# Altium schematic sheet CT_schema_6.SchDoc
size 255 x 245 mm
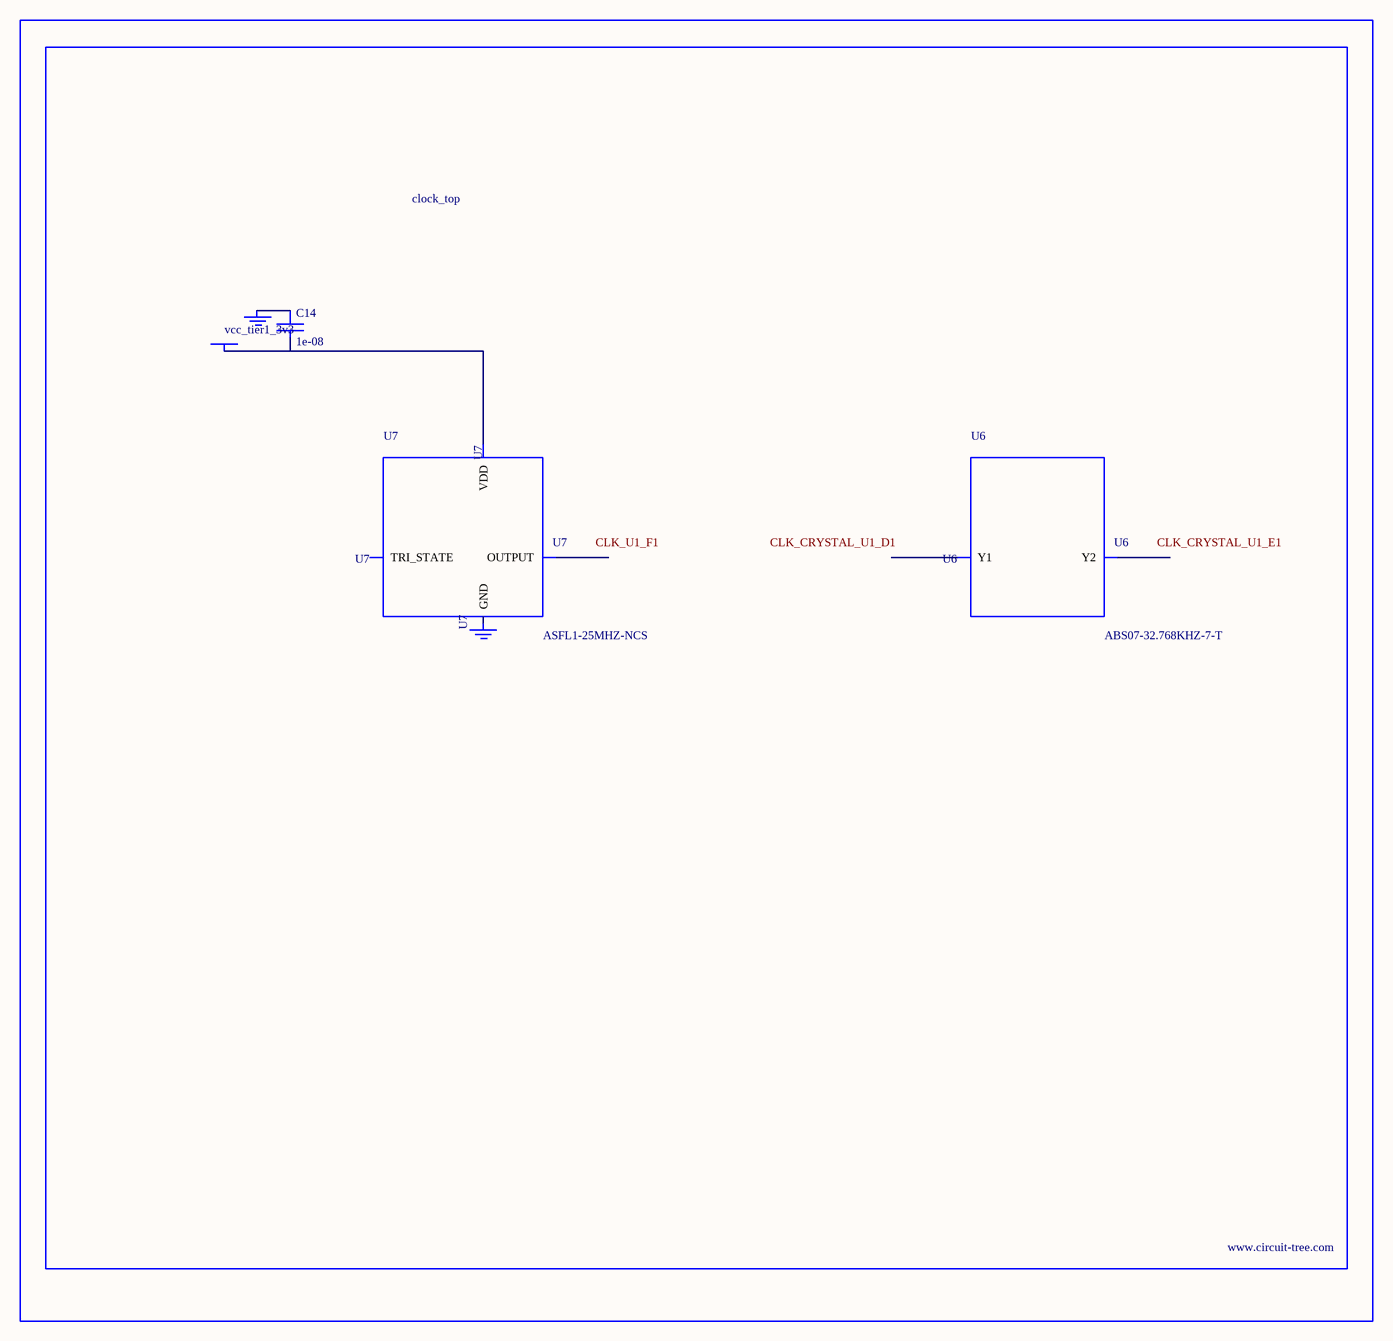
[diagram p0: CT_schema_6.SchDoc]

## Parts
BORDER5  (no value)
C14  1e-08  [C0402]
GND_INSTANCE_5_0  (no value)
GND_INSTANCE_5_1  (no value)
POWER_INSTANCE_5_0  vcc_tier1_3v3
U6  ABS07-32.768KHZ-7-T  [ABS07-32.768KHZ-7-T]
U7  ASFL1-25MHZ-NCS  [ASFL1]

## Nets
NetC14_1: C14.1 GND_INSTANCE_5_0.0(GND)
NetC14_2: C14.2 POWER_INSTANCE_5_0.0(PWR) U7.4(VDD)

Not connected (* = marked no-connect by the designer): GND_INSTANCE_5_1 0(GND); U6 1(Y1) 2(Y2); U7 1(TRI_STATE) 2(GND) 3(OUTPUT)

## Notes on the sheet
- Labels drawn without touching a wire or pin: CLK_CRYSTAL_U1_D1, CLK_CRYSTAL_U1_E1, CLK_U1_F1

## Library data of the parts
BORDER5 = BORDER_PAGE5
C14 = C0402C103K3RAC
GND_INSTANCE_5_0 GND_INSTANCE_5_1 = GND
POWER_INSTANCE_5_0 = PWR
